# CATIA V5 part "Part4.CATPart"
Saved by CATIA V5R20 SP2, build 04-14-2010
Part number: Part4
Bounding box of the stored display mesh (mm): x -20 to 20, y -14.119 to 167.761, z 82.437 to 124.337
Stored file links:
  E:\CATIA\New folder\Part4.CATPart
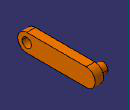
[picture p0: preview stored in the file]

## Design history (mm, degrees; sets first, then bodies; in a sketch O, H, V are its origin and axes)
Body1 (main body)
  Sketch1 on yz-plane, origin (0, 0, 0), H (0, 1, 0), V (0, 0, 1)
    construction line L1 (6.8209, 103.3865) -> (146.8209, 103.3865)
    line L2 (6.8209, 124.3365) -> (146.8209, 124.3365)
    line L3 (146.8209, 82.4365) -> (6.8209, 82.4365)
    arc A1 centre (146.8209, 103.3865) radius 20.95 from (146.8209, 124.3365) to (146.8209, 82.4365) cw
    arc A2 centre (6.8209, 103.3865) radius 20.95 from (6.8209, 82.4365) to (6.8209, 124.3365) cw
    circle A3 centre (146.8209, 103.3865) radius 11.04
    circle A4 centre (6.8209, 103.3865) radius 11.04
  MultiPad1: profile Sketch1, domains (length 20; length 0; length 20 / length 20)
